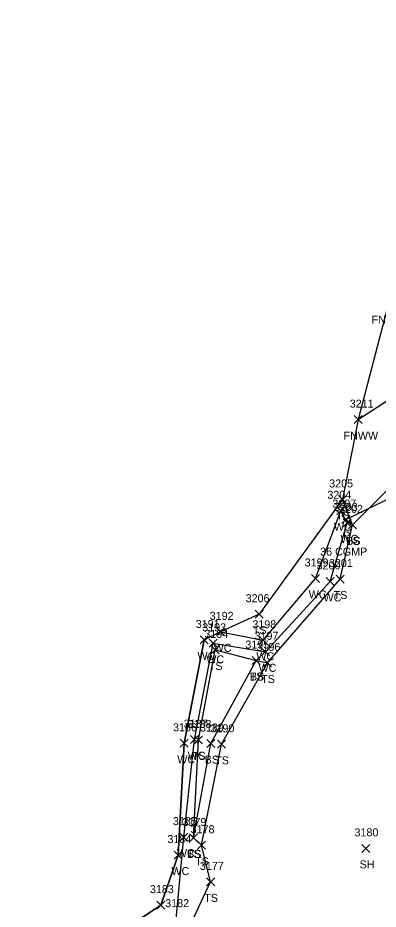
# Model space of a CAD drawing. Extents: x 1623612 to 1625808, y 621345 to 627748.
# Drawn here: x 1624980.5 to 1625070.4, y 627315.5 to 627538.2 of the extents above; entities that cross this region are included whole.
import ezdxf

# ---------------------------------------------------------------- set-up
doc = ezdxf.new("R2010")
doc.units = 0
for name, color, linetype in [('D_A', 7, 'Continuous'), ('D_C', 7, 'Continuous'), ('D_I', 7, 'Continuous'), ('D_TIC', 7, 'Continuous'), ('DCP', 7, 'Continuous'), ('L_A', 7, 'Continuous'), ('L_I', 7, 'Continuous'), ('L_TIC', 7, 'Continuous'), ('LAWE', 7, 'Continuous'), ('LELB', 7, 'Continuous'), ('LFNC', 7, 'Continuous'), ('LSOGP', 7, 'Continuous')]:
    doc.layers.add(name, color=color, linetype=linetype)

msp = doc.modelspace()

# ---------------------------------------------------------------- linework, layer by layer
at = {"layer": 'D_TIC'}
for points in [[(1625061.29, 627411.82), (1625063.29, 627413.82)], [(1625063.29, 627411.82), (1625061.29, 627413.82)]]:
    msp.add_lwpolyline(points, dxfattribs=at)
at = {"layer": 'DCP'}
msp.add_lwpolyline([(1625062.29, 627412.82), (1625238.51, 627498.84)], dxfattribs=at)
at = {"layer": 'L_TIC'}
for points in [[(1625064.43, 627436.81), (1625066.43, 627438.81)], [(1625066.43, 627436.81), (1625064.43, 627438.81)], [(1625060.51, 627416.86), (1625062.51, 627418.86)], [(1625062.51, 627416.86), (1625060.51, 627418.86)], [(1625060.06, 627414.02), (1625062.06, 627416.02)], [(1625062.06, 627414.02), (1625060.06, 627416.02)], [(1625060.06, 627414.02), (1625062.06, 627416.02)], [(1625062.06, 627414.02), (1625060.06, 627416.02)], [(1625061.67, 627411), (1625063.67, 627413)], [(1625063.67, 627411), (1625061.67, 627413)], [(1625062.98, 627410.51), (1625064.98, 627412.51)], [(1625064.98, 627410.51), (1625062.98, 627412.51)], [(1625062.98, 627410.51), (1625064.98, 627412.51)], [(1625064.98, 627410.51), (1625062.98, 627412.51)], [(1625053.76, 627397.11), (1625055.76, 627399.11)], [(1625055.76, 627397.11), (1625053.76, 627399.11)], [(1625057.44, 627396.37), (1625059.44, 627398.37)], [(1625059.44, 627396.37), (1625057.44, 627398.37)], [(1625059.88, 627396.97), (1625061.88, 627398.97)], [(1625061.88, 627396.97), (1625059.88, 627398.97)], [(1625039.72, 627388.17), (1625041.72, 627390.17)], [(1625041.72, 627388.17), (1625039.72, 627390.17)], [(1625030.05, 627383.77), (1625032.05, 627385.77)], [(1625032.05, 627383.77), (1625030.05, 627385.77)], [(1625026, 627381.74), (1625028, 627383.74)], [(1625028, 627381.74), (1625026, 627383.74)], [(1625028.2, 627380.9), (1625030.2, 627382.9)], [(1625030.2, 627380.9), (1625028.2, 627382.9)], [(1625040.7, 627381.66), (1625042.7, 627383.66)], [(1625042.7, 627381.66), (1625040.7, 627383.66)], [(1625028.73, 627379.24), (1625030.73, 627381.24)], [(1625030.73, 627379.24), (1625028.73, 627381.24)], [(1625041.24, 627378.78), (1625043.24, 627380.78)], [(1625043.24, 627378.78), (1625041.24, 627380.78)], [(1625038.96, 627376.6), (1625040.96, 627378.6)], [(1625040.96, 627376.6), (1625038.96, 627378.6)], [(1625038.96, 627376.6), (1625040.96, 627378.6)], [(1625040.96, 627376.6), (1625038.96, 627378.6)], [(1625041.79, 627375.99), (1625043.79, 627377.99)], [(1625043.79, 627375.99), (1625041.79, 627377.99)], [(1625041.79, 627375.99), (1625043.79, 627377.99)], [(1625043.79, 627375.99), (1625041.79, 627377.99)], [(1625020.97, 627355.92), (1625022.97, 627357.92)], [(1625022.97, 627355.92), (1625020.97, 627357.92)], [(1625023.55, 627356.83), (1625025.55, 627358.83)], [(1625025.55, 627356.83), (1625023.55, 627358.83)], [(1625024.55, 627356.74), (1625026.55, 627358.74)], [(1625026.55, 627356.74), (1625024.55, 627358.74)], [(1625027.65, 627355.85), (1625029.65, 627357.85)], [(1625029.65, 627355.85), (1625027.65, 627357.85)], [(1625030.34, 627355.66), (1625032.34, 627357.66)], [(1625032.34, 627355.66), (1625030.34, 627357.66)], [(1625020.87, 627332.46), (1625022.87, 627334.46)], [(1625022.87, 627332.46), (1625020.87, 627334.46)], [(1625023.29, 627332.27), (1625025.29, 627334.27)], [(1625025.29, 627332.27), (1625023.29, 627334.27)], [(1625023.29, 627332.27), (1625025.29, 627334.27)], [(1625025.29, 627332.27), (1625023.29, 627334.27)], [(1625025.31, 627330.44), (1625027.31, 627332.44)], [(1625027.31, 627330.44), (1625025.31, 627332.44)], [(1625025.31, 627330.44), (1625027.31, 627332.44)], [(1625027.31, 627330.44), (1625025.31, 627332.44)], [(1625066.28, 627329.65), (1625068.28, 627331.65)], [(1625068.28, 627329.65), (1625066.28, 627331.65)], [(1625019.5, 627327.97), (1625021.5, 627329.97)], [(1625021.5, 627327.97), (1625019.5, 627329.97)], [(1625027.6, 627321.27), (1625029.6, 627323.27)], [(1625029.6, 627321.27), (1625027.6, 627323.27)], [(1625015.13, 627315.47), (1625017.13, 627317.47)], [(1625017.13, 627315.47), (1625015.13, 627317.47)]]:
    msp.add_lwpolyline(points, dxfattribs=at)
at = {"layer": 'LAWE'}
for points in [[(1624950.82, 627105.47), (1624955.57, 627132.71), (1624970.42, 627171.42), (1624974.37, 627214.03), (1624986.78, 627235.69), (1624993.38, 627267.64), (1624994.62, 627302.25), (1625016.13, 627316.47), (1625020.5, 627328.97), (1625021.97, 627356.92), (1625027, 627382.74), (1625031.05, 627384.77), (1625041.7, 627382.66), (1625054.76, 627398.11), (1625061.06, 627415.02)], [(1624954.66, 627105.91), (1624958.35, 627132.16), (1624972.4, 627170.37), (1624983.53, 627207.29), (1624975.9, 627214.09), (1624988.65, 627235.54), (1624997.99, 627265.89), (1624995.74, 627270.39), (1624996.84, 627300.29), (1625009.29, 627304.15), (1625019.96, 627312.96), (1625021.87, 627333.46), (1625024.55, 627357.83), (1625029.2, 627381.9), (1625042.24, 627379.78), (1625058.44, 627397.37), (1625062.67, 627412), (1625061.06, 627415.02)]]:
    msp.add_lwpolyline(points, dxfattribs=at)
at = {"layer": 'LELB'}
for points in [[(1625063.98, 627411.51), (1625081.28, 627428.81), (1625097.38, 627452.83)], [(1624960.51, 627103.98), (1624966.27, 627131.21), (1624976.01, 627168.33), (1624986.98, 627206.27), (1624976.96, 627214.4), (1624989.83, 627234.41), (1625000.45, 627265.06), (1624996.69, 627269.86), (1624998.17, 627299.41), (1625010.1, 627302.1), (1625013.35, 627301.95), (1625021.07, 627306.21), (1625028.6, 627322.27), (1625026.31, 627331.44), (1625024.29, 627333.27), (1625025.55, 627357.74), (1625029.73, 627380.24), (1625039.96, 627377.6), (1625042.79, 627376.99), (1625060.88, 627397.97), (1625063.98, 627411.51), (1625061.51, 627417.86), (1625040.72, 627389.17)], [(1625024.29, 627333.27), (1625028.65, 627356.85), (1625039.96, 627377.6)], [(1625026.31, 627331.44), (1625031.34, 627356.66), (1625042.79, 627376.99)]]:
    msp.add_lwpolyline(points, dxfattribs=at)
at = {"layer": 'LFNC'}
msp.add_lwpolyline([(1625065.43, 627437.81), (1625102.56, 627462.03)], dxfattribs=at)
at = {"layer": 'LSOGP'}
msp.add_lwpolyline([(1625111.66, 627549.52), (1625108.47, 627513.68), (1625102.56, 627462.03), (1625072.98, 627466.8), (1625065.43, 627437.81), (1625061.51, 627417.86), (1625040.72, 627389.17), (1625031.05, 627384.77), (1625027, 627382.74), (1625021.97, 627356.92), (1625020.5, 627328.97), (1625016.13, 627316.47), (1624994.62, 627302.25), (1624993.38, 627267.64), (1624986.78, 627235.69), (1624974.37, 627214.03), (1624949.62, 627201.5), (1624918.99, 627198.08), (1624909.18, 627186.43), (1624915.57, 627163.54), (1624896.56, 627076.5)], dxfattribs=at)

# ---------------------------------------------------------------- texts
at = {"layer": 'D_A'}
msp.add_text('P', height=2, dxfattribs=at).set_placement((1625061.67, 627407.82))
at = {"layer": 'D_C'}
msp.add_text('36 CGMP', height=2, dxfattribs=at).set_placement((1625055.92, 627403.82))
at = {"layer": 'D_I'}
msp.add_text('3207', height=2, dxfattribs=at).set_placement((1625058.95, 627415.82))
at = {"layer": 'L_A'}
for s, p in [('FNCHL', (1625068.73, 627461.8)), ('FNWW', (1625061.77, 627432.81)), ('TS', (1625059.92, 627412.86)), ('WC', (1625059.37, 627410.02)), ('WC', (1625059.37, 627410.02)), ('WC', (1625060.98, 627407)), ('TS', (1625062.39, 627406.51)), ('BS', (1625062.42, 627406.51)), ('WC', (1625053.07, 627393.11)), ('TS', (1625059.29, 627392.97)), ('WC', (1625056.75, 627392.37)), ('TS', (1625039.13, 627384.17)), ('WC', (1625029.36, 627379.77)), ('WC', (1625025.31, 627377.74)), ('WC', (1625040, 627377.66)), ('WC', (1625027.5, 627376.9)), ('TS', (1625028.14, 627375.24)), ('WC', (1625040.55, 627374.78)), ('TS', (1625038.37, 627372.6)), ('BS', (1625038.4, 627372.6)), ('TS', (1625041.2, 627371.99)), ('TS', (1625041.2, 627371.99)), ('WC', (1625020.27, 627351.92)), ('WC', (1625022.86, 627352.83)), ('TS', (1625023.96, 627352.74)), ('BS', (1625027.1, 627351.85)), ('TS', (1625029.75, 627351.66)), ('WC', (1625020.18, 627328.46)), ('TS', (1625022.69, 627328.27)), ('BS', (1625022.73, 627328.27)), ('TS', (1625024.72, 627326.44)), ('TS', (1625024.72, 627326.44)), ('WC', (1625018.81, 627323.97)), ('SH', (1625065.77, 627325.65)), ('TS', (1625027.01, 627317.27))]:
    msp.add_text(s, height=2, dxfattribs=at).set_placement(p)
at = {"layer": 'L_I'}
for s, p in [('3211', (1625063.3, 627440.81)), ('3205', (1625058.17, 627420.86)), ('3204', (1625057.72, 627418.02)), ('3204', (1625057.72, 627418.02)), ('3203', (1625059.33, 627415)), ('3202', (1625060.64, 627414.51)), ('3202', (1625060.64, 627414.51)), ('3199', (1625052.06, 627401.11)), ('3200', (1625055.02, 627400.37)), ('3201', (1625058.11, 627400.97)), ('3206', (1625037.33, 627392.17)), ('3192', (1625028.36, 627387.77)), ('3191', (1625024.88, 627385.74)), ('3193', (1625026.5, 627384.9)), ('3198', (1625039, 627385.66)), ('3194', (1625027.03, 627383.24)), ('3197', (1625039.55, 627382.78)), ('3195', (1625037.27, 627380.6)), ('3195', (1625037.27, 627380.6)), ('3196', (1625040.04, 627379.99)), ('3196', (1625040.04, 627379.99)), ('3186', (1625019.22, 627359.92)), ('3187', (1625021.86, 627360.83)), ('3188', (1625022.85, 627360.74)), ('3189', (1625025.95, 627359.85)), ('3190', (1625028.56, 627359.66)), ('3185', (1625019.18, 627336.46)), ('3179', (1625021.58, 627336.27)), ('3179', (1625021.58, 627336.27)), ('3178', (1625023.61, 627334.44)), ('3178', (1625023.61, 627334.44)), ('3180', (1625064.5, 627333.65)), ('3184', (1625017.81, 627331.97)), ('3177', (1625025.91, 627325.27)), ('3183', (1625013.44, 627319.47)), ('3182', (1625017.26, 627315.96))]:
    msp.add_text(s, height=2, dxfattribs=at).set_placement(p)

doc.saveas('drawing.dxf')
